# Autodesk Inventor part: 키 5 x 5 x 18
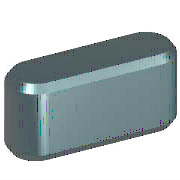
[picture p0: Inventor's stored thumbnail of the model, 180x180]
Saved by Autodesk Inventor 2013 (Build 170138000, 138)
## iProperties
Created: 2012-02
Part Number: 키 5 x 5 x 18
Material: 강철, 연강
Description: 키 및 해당 키홈
Document SubType Name: Modeling
Standard: KS B 1311
Designer: mduedu
Standards Organization: KS
Language: ko-KR
Size Designation: 5 x 5 x 18
Categories: <MemberInstance><Categories><Category DisplayName="샤프트 부품" InternalName="7f7aeb1f-a693-4053-b835-cee3144e0d98" Mnemonic="SHFT"><Category DisplayName="키" Interna
Density: 1 g/cm^3
IsCustomPart: 1
Author: mduedu
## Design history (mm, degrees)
workplane "Work Plane1"
workplane "Work Plane2"
sketch "스케치1"
  geometry: L1 (2.5, 2.5)-(15.5, 2.5); L2 (15.5, -2.5)-(2.5, -2.5); L3 (0, 9.4)-(0, -7.4) reference; L4 (-5, 0)-(30, 0) reference; L5 (18, 0)-(18, 7); A1 r 2.5 centre (2.5, 0) between (2.5, 2.5) and (2.5, -2.5); A2 r 2.5 centre (15.5, 0) between (15.5, -2.5) and (15.5, 2.5)
  constraints: 6 end point, 5 point on circle, 4 tangent, 3 point on line, 2 centre point, 1 horizontal, 1 parallel, 1 perpendicular
  dimensions: "d0" = 2.5 radius of A1 (= 0.5 x PB); "d13" = 2.5 radius of A2 (= 0.5 x PB); "d14" = 18 distance between parallel lines of L5 L3 (= NLG)
extrude "본체1" new body sketch "스케치1" taper "d3" = 0 deg; stored distance "d4" = 10
workplane "Work Plane3"
body "Solid1"
chamfer "모따기1" distance "d8" = 0.4 (= PHH); stored, may be unused: second distance "d9" = 0.4 (= PHH), angle "d15" = 45 deg
other parameters: "d1" = -3 (= -PNT), "d2" = 2 (= PH - PNT), "NLG" = 18 [user parameter; used in 3 equation terms], "PB" = 5 [user parameter; used in 2 equation terms], "PNT" = 3 [user parameter; used in 2 equation terms], "PH" = 5 [user parameter; used in 1 equation term], "PHH" = 0.4 [user parameter; used in 2 equation terms], "d10" = 0, "d16" = 0, "d17" = 0, "d18" = 0, "WDMIN" = 12 [user parameter], "PLB2" = 18 (= NLG) [user parameter], "WDMAX" = 17 [user parameter], "PLB1" = 18 (= NLG) [user parameter], "RR" = 0.16 [user parameter], "PUEB" = 2.3 [user parameter]
